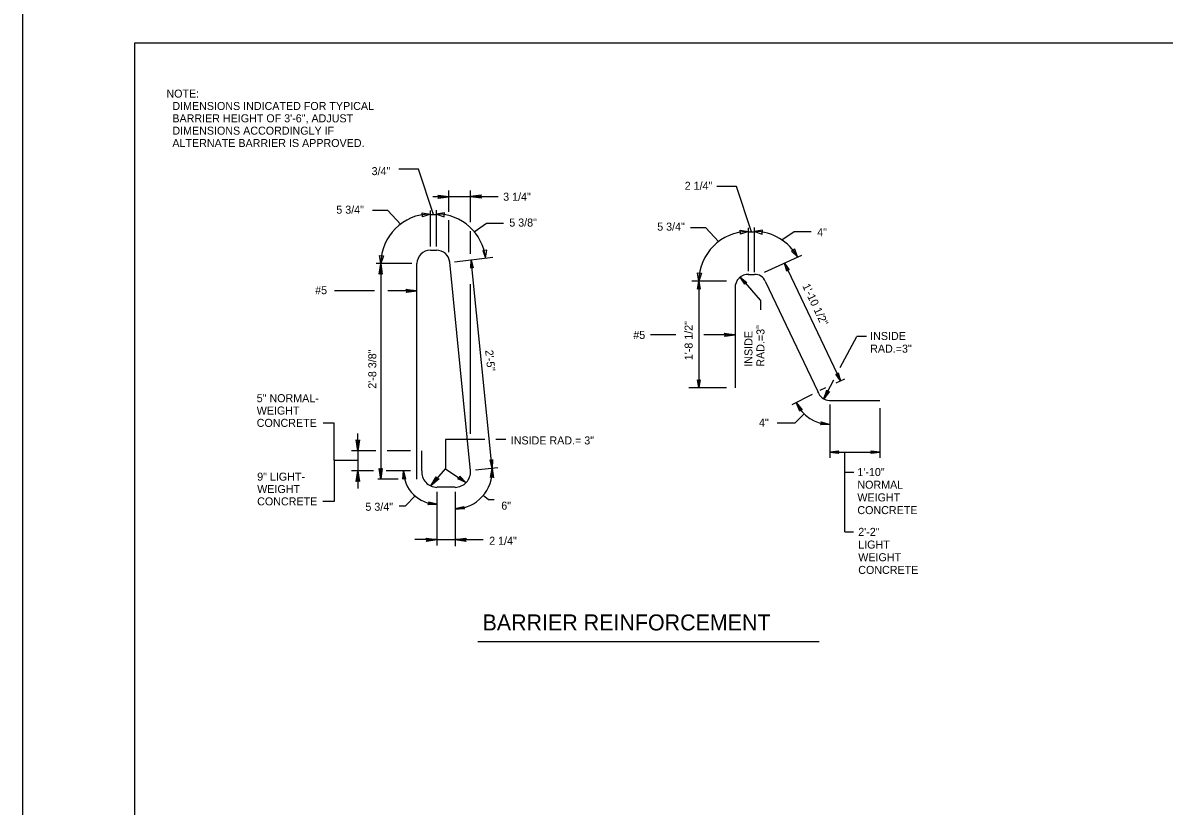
# Model space of a CAD drawing. Extents: x -24512 to -22484, y 4569 to 6351.
# Drawn here: x -24179.8 to -23752.2, y 4862.3 to 5155.5 of the extents above; entities that cross this region are included whole.
import ezdxf

# ---------------------------------------------------------------- set-up
doc = ezdxf.new("R2010")
doc.units = 0
for name, color, linetype in [('10', 7, 'Continuous'), ('11', 7, 'Continuous'), ('2', 7, 'Continuous'), ('PLT-BNDY', 7, 'Continuous')]:
    doc.layers.add(name, color=color, linetype=linetype)

msp = doc.modelspace()

# ---------------------------------------------------------------- linework, layer by layer
at = {"layer": '10'}
msp.add_arc((-24024.54, 4987.88), 12.58, 180.3102, 269.7376, dxfattribs=at)
at = {"layer": '11'}
msp.add_line((-24009.29, 4923.94), (-23881.36, 4923.94), dxfattribs=at)
at = {"layer": '2'}
for p, q in [((-24137.79, 5148.04), (-23353.75, 5148.04)), ((-24137.79, 4584.04), (-24137.79, 5148.04)), ((-24031.48, 5100.79), (-24038.95, 5100.79)), ((-24025.88, 5083.82), (-24031.48, 5100.79)), ((-24020.1, 5084.77), (-24020.1, 5092.81)), ((-24012.1, 5080.97), (-24012.1, 5092.81)), ((-23912.34, 5094.25), (-23919.81, 5094.25)), ((-23906.74, 5077.28), (-23912.34, 5094.25)), ((-24020.1, 5090.43), (-24026.19, 5090.43)), ((-24020.1, 5090.56), (-24020.1, 5090.56)), ((-24020.1, 5090.56), (-24012.1, 5090.56)), ((-24012.1, 5090.56), (-24012.1, 5090.56)), ((-24012.1, 5090.56), (-24001.73, 5090.56)), ((-24012.1, 5090.43), (-24012.1, 5090.43)), ((-24042.98, 5085.32), (-24048.81, 5085.32)), ((-24038.26, 5080.2), (-24042.98, 5085.32)), ((-24027.09, 5071.78), (-24027.09, 5085.33)), ((-24024.8, 5071.78), (-24024.8, 5085.42)), ((-24027.09, 5083.82), (-24024.8, 5083.82)), ((-24020.1, 5069.69), (-24020.1, 5081.65)), ((-24010.63, 5077.36), (-24006.04, 5080.56)), ((-24006.04, 5080.56), (-23999.66, 5080.56)), ((-24012.1, 5069.01), (-24012.1, 5077.57)), ((-23923.84, 5078.77), (-23929.68, 5078.77)), ((-23919.12, 5073.66), (-23923.84, 5078.77)), ((-23907.95, 5062.57), (-23907.95, 5078.78)), ((-23907.95, 5077.28), (-23905.66, 5077.28)), ((-23905.66, 5062.21), (-23905.66, 5078.88)), ((-23895.37, 5074.29), (-23890.78, 5077.49)), ((-23890.78, 5077.49), (-23884.4, 5077.49)), ((-24027.09, 5070.43), (-24024.8, 5070.43)), ((-24026.1, 5070.43), (-24026.1, 5070.43)), ((-24018.06, 5066.07), (-24003.67, 5067.79)), ((-23901.86, 5062.17), (-23887.96, 5068.61)), ((-24034, 5065.43), (-24047.39, 5065.43)), ((-24045.59, 5065.43), (-24045.59, 4984.68)), ((-24032.09, 4984.68), (-24032.09, 5065.43)), ((-24012.1, 4987.81), (-24019.82, 5065.92)), ((-24003.98, 4988.68), (-24011.78, 5066.82)), ((-23894.45, 5065.56), (-23873.45, 5021.56)), ((-23916.08, 5058.81), (-23929.14, 5058.81)), ((-23926.51, 5058.81), (-23926.51, 5018.93)), ((-23903.43, 5051.78), (-23910.68, 5060.03)), ((-23907.95, 5061.35), (-23905.66, 5061.35)), ((-23907.95, 5061.35), (-23905.66, 5061.35)), ((-23901.63, 5058.79), (-23881.95, 5017.56)), ((-24048.02, 5055.22), (-24063, 5055.22)), ((-24032.09, 5055.22), (-24042.98, 5055.22)), ((-24012.1, 5001.68), (-24012.1, 5057.65)), ((-23912.93, 5056.53), (-23912.95, 5018.93)), ((-23906.7, 5055.93), (-23906.7, 5055.93)), ((-23903.43, 5051.78), (-23903.43, 5048.05)), ((-23935.13, 5038.72), (-23944.61, 5038.72)), ((-23912.94, 5038.72), (-23924.6, 5038.72)), ((-23873.5, 5026.53), (-23867.32, 5038.18)), ((-23863.7, 5038.18), (-23867.32, 5038.18)), ((-23879.7, 5014.81), (-23875.92, 5021.92)), ((-23875.2, 5020.81), (-23875.2, 5020.81)), ((-23875.04, 5020.79), (-23871.82, 5022.31)), ((-23916.08, 5018.93), (-23930.29, 5018.93)), ((-23921.07, 5018.93), (-23921.07, 5018.93)), ((-23912.95, 5018.93), (-23912.95, 5018.93)), ((-23912.95, 5018.93), (-23912.95, 5018.93)), ((-23891.57, 5012.68), (-23883.86, 5016.54)), ((-23881, 5017.97), (-23878.94, 5019)), ((-23877.45, 5018.93), (-23877.45, 5018.93)), ((-23879.57, 5014.68), (-23879.57, 5014.68)), ((-23877.45, 5014.18), (-23858.7, 5014.18)), ((-23877.45, 5014.18), (-23877.45, 5014.18)), ((-23877.45, 5014.18), (-23877.45, 5014.18)), ((-23877.45, 5012.68), (-23877.45, 4992.94)), ((-23877.45, 5011.33), (-23877.45, 4992.73)), ((-23858.7, 5014.18), (-23858.7, 5014.18)), ((-23858.7, 5011.33), (-23858.7, 4992.73)), ((-23887.19, 5009.06), (-23890.42, 5005.79)), ((-24063.08, 5005.68), (-24067.21, 5005.68)), ((-24063.08, 4991.68), (-24063.08, 5005.68)), ((-23897.16, 5005.79), (-23890.42, 5005.79)), ((-24054.21, 4995.31), (-24054.21, 5001.79)), ((-24021.35, 4999.56), (-24021.35, 4988.56)), ((-24006.73, 4999.56), (-24021.35, 4999.56)), ((-23998.85, 4999.56), (-24002.6, 4999.56)), ((-24047.56, 4995.31), (-24056.59, 4995.31)), ((-24054.21, 4995.31), (-24054.21, 4981.24)), ((-24034.57, 4995.31), (-24043.21, 4995.31)), ((-24037.34, 4995.31), (-24037.34, 4995.31)), ((-24030.32, 4987.89), (-24030.32, 4995.31)), ((-23877.45, 4994.85), (-23858.7, 4994.85)), ((-23877.45, 4994.85), (-23877.45, 4994.85)), ((-23871.82, 4964.99), (-23871.82, 4994.73)), ((-23858.7, 4994.85), (-23858.7, 4994.85)), ((-24054.21, 4991.68), (-24063.08, 4991.68)), ((-24063.08, 4991.68), (-24063.08, 4976.31)), ((-24048.34, 4987.81), (-24056.59, 4987.81)), ((-24034.57, 4987.81), (-24043.59, 4987.81)), ((-24026.88, 4982.16), (-24021.35, 4988.56)), ((-24021.35, 4988.56), (-24013.73, 4983.43)), ((-24012.1, 4987.81), (-24012.1, 4987.81)), ((-24010.23, 4988.18), (-24001.85, 4989.06)), ((-24003.98, 4988.93), (-24003.98, 4988.93)), ((-23871.82, 4987.35), (-23868.45, 4987.35)), ((-24039.1, 4984.68), (-24046.7, 4984.68)), ((-24032.09, 4984.68), (-24032.09, 4984.68)), ((-24026.1, 4983.06), (-24026.1, 4983.06)), ((-24017.73, 4981.68), (-24024.6, 4981.68)), ((-24022.6, 4981.68), (-24022.6, 4981.68)), ((-24018.85, 4981.68), (-24018.85, 4981.68)), ((-24017.73, 4981.68), (-24017.73, 4981.68)), ((-24013.73, 4983.43), (-24013.73, 4983.43)), ((-24036.34, 4974.68), (-24032.79, 4978.49)), ((-24024.6, 4979.93), (-24024.6, 4959.93)), ((-24017.73, 4979.93), (-24017.73, 4959.68)), ((-24005.35, 4976.93), (-24007.27, 4978.6)), ((-24063.08, 4976.31), (-24067.33, 4976.31)), ((-24038.77, 4974.68), (-24036.34, 4974.68)), ((-24003.23, 4976.93), (-24005.35, 4976.93)), ((-23871.82, 4964.99), (-23868.57, 4964.99)), ((-24024.6, 4962.06), (-24032.85, 4962.06)), ((-24024.6, 4962.06), (-24007.35, 4962.06)), ((-24017.73, 4962.06), (-24017.73, 4962.06))]:
    msp.add_line(p, q, dxfattribs=at)
for points in [[(-24024.1, 5090.93), (-24023.85, 5090.56), (-24020.1, 5090.43), (-24024.1, 5090.93), (-24024.23, 5091.06), (-24020.1, 5090.43), (-24023.85, 5090.31), (-24024.1, 5089.93), (-24020.1, 5090.43), (-24024.23, 5089.81), (-24024.1, 5089.93)], [(-24024.1, 5090.93), (-24023.85, 5090.56), (-24020.1, 5090.43), (-24024.1, 5090.93), (-24024.23, 5091.06), (-24020.1, 5090.43), (-24023.85, 5090.31), (-24024.1, 5089.93), (-24020.1, 5090.43), (-24024.23, 5089.81), (-24024.1, 5089.93)], [(-24008.1, 5090.06), (-24008.35, 5090.43), (-24012.1, 5090.56), (-24008.1, 5090.06), (-24007.98, 5089.93), (-24012.1, 5090.56), (-24008.35, 5090.68), (-24008.1, 5091.06), (-24012.1, 5090.56), (-24007.98, 5091.18), (-24008.1, 5091.06)], [(-24046.09, 5061.56), (-24045.84, 5061.68), (-24045.59, 5065.43), (-24046.09, 5061.56), (-24046.21, 5061.43), (-24045.59, 5065.43), (-24045.46, 5061.68), (-24045.21, 5061.56), (-24045.59, 5065.43), (-24045.09, 5061.43), (-24045.21, 5061.56)], [(-24011.91, 5063.94), (-24011.66, 5064.07), (-24011.78, 5066.82), (-24011.91, 5063.94), (-24011.91, 5063.69), (-24011.78, 5066.82), (-24011.41, 5064.07), (-24011.16, 5063.94), (-24011.78, 5066.82), (-24011.03, 5063.82), (-24011.16, 5063.94)], [(-23893.57, 5062.81), (-23893.32, 5062.93), (-23894.45, 5065.56), (-23893.57, 5062.81), (-23893.57, 5062.56), (-23894.45, 5065.56), (-23893.07, 5063.06), (-23892.95, 5063.06), (-23894.45, 5065.56), (-23892.7, 5063.06), (-23892.95, 5063.06)], [(-23926.89, 5055.93), (-23926.64, 5056.06), (-23926.51, 5058.81), (-23926.89, 5055.93), (-23927.01, 5055.81), (-23926.51, 5058.81), (-23926.39, 5056.06), (-23926.14, 5055.93), (-23926.51, 5058.81), (-23926.01, 5055.81), (-23926.14, 5055.93)], [(-23909.33, 5057.99), (-23909.21, 5058.11), (-23910.96, 5060.36), (-23909.33, 5057.99), (-23909.33, 5057.74), (-23910.96, 5060.36), (-23908.96, 5058.36), (-23908.83, 5058.36), (-23910.96, 5060.36), (-23908.58, 5058.36), (-23908.83, 5058.36)], [(-24035.96, 5055.6), (-24035.84, 5055.35), (-24032.09, 5055.22), (-24035.96, 5055.6), (-24036.09, 5055.85), (-24032.09, 5055.22), (-24035.84, 5055.1), (-24035.96, 5054.72), (-24032.09, 5055.22), (-24036.09, 5054.6), (-24035.96, 5054.72)], [(-23916.82, 5039.1), (-23916.69, 5038.85), (-23912.94, 5038.72), (-23916.82, 5039.1), (-23916.94, 5039.35), (-23912.94, 5038.72), (-23916.69, 5038.6), (-23916.82, 5038.22), (-23912.94, 5038.72), (-23916.94, 5038.1), (-23916.82, 5038.22)], [(-23874.32, 5024.31), (-23874.57, 5024.18), (-23873.45, 5021.56), (-23874.32, 5024.31), (-23874.32, 5024.56), (-23873.45, 5021.56), (-23874.82, 5024.06), (-23874.95, 5024.06), (-23873.45, 5021.56), (-23875.2, 5024.06), (-23874.95, 5024.06)], [(-23926.14, 5021.81), (-23926.39, 5021.68), (-23926.51, 5018.93), (-23926.14, 5021.81), (-23926.01, 5021.93), (-23926.51, 5018.93), (-23926.64, 5021.68), (-23926.89, 5021.81), (-23926.51, 5018.93), (-23927.01, 5021.93), (-23926.89, 5021.81)], [(-23877.82, 5017.43), (-23878.07, 5017.43), (-23879.7, 5014.81), (-23877.82, 5017.43), (-23877.57, 5017.56), (-23879.7, 5014.81), (-23878.32, 5017.56), (-23878.57, 5017.81), (-23879.7, 5014.81), (-23878.57, 5018.06), (-23878.57, 5017.81)], [(-23888.65, 5010.38), (-23888.5, 5010.61), (-23890, 5013.35), (-23888.65, 5010.38), (-23888.7, 5010.2), (-23890, 5013.35), (-23888.29, 5010.74), (-23888.01, 5010.76), (-23890, 5013.35), (-23887.84, 5010.72), (-23888.01, 5010.76)], [(-23880.7, 5006), (-23880.53, 5005.78), (-23877.49, 5005.22), (-23880.7, 5006), (-23880.73, 5006.12), (-23877.49, 5005.22), (-23880.58, 5005.39), (-23880.68, 5005.24), (-23877.49, 5005.22), (-23880.9, 5005.07), (-23880.68, 5005.24)], [(-24053.71, 4999.18), (-24054.09, 4999.06), (-24054.21, 4995.31), (-24053.71, 4999.18), (-24053.59, 4999.43), (-24054.21, 4995.31), (-24054.34, 4999.06), (-24054.59, 4999.18), (-24054.21, 4995.31), (-24054.84, 4999.43), (-24054.59, 4999.18)], [(-23874.2, 4994.48), (-23874.32, 4994.73), (-23877.45, 4994.85), (-23874.2, 4994.48), (-23874.07, 4994.35), (-23877.45, 4994.85), (-23874.32, 4994.98), (-23874.2, 4995.23), (-23877.45, 4994.85), (-23874.07, 4995.35), (-23874.2, 4995.23)], [(-23874.2, 4994.48), (-23874.32, 4994.73), (-23877.45, 4994.85), (-23874.2, 4994.48), (-23874.07, 4994.35), (-23877.45, 4994.85), (-23874.32, 4994.98), (-23874.2, 4995.23), (-23877.45, 4994.85), (-23874.07, 4995.35), (-23874.2, 4995.23)], [(-23861.95, 4995.23), (-23861.82, 4994.98), (-23858.7, 4994.85), (-23861.95, 4995.23), (-23862.07, 4995.35), (-23858.7, 4994.85), (-23861.82, 4994.73), (-23861.95, 4994.48), (-23858.7, 4994.85), (-23862.07, 4994.35), (-23861.95, 4994.48)], [(-24003.85, 4991.81), (-24004.1, 4991.68), (-24003.98, 4988.68), (-24003.85, 4991.81), (-24003.85, 4992.06), (-24003.98, 4988.68), (-24004.35, 4991.68), (-24004.6, 4991.81), (-24003.98, 4988.68), (-24004.73, 4991.93), (-24004.6, 4991.81)], [(-24054.59, 4983.93), (-24054.34, 4984.06), (-24054.21, 4987.81), (-24054.59, 4983.93), (-24054.84, 4983.81), (-24054.21, 4987.81), (-24054.09, 4984.06), (-24053.71, 4983.93), (-24054.21, 4987.81), (-24053.59, 4983.81), (-24053.71, 4983.93)], [(-24045.21, 4988.56), (-24045.46, 4988.43), (-24045.59, 4984.68), (-24045.21, 4988.56), (-24045.09, 4988.68), (-24045.59, 4984.68), (-24045.84, 4988.43), (-24046.09, 4988.56), (-24045.59, 4984.68), (-24046.21, 4988.68), (-24046.09, 4988.56)], [(-24037.24, 4984.79), (-24037, 4984.93), (-24037.12, 4987.81), (-24037.24, 4984.79), (-24037.36, 4984.65), (-24037.12, 4987.81), (-24036.75, 4984.95), (-24036.49, 4984.85), (-24037.12, 4987.81), (-24036.36, 4984.74), (-24036.49, 4984.85)], [(-24016.1, 4985.56), (-24016.1, 4985.43), (-24013.73, 4983.43), (-24016.1, 4985.56), (-24016.1, 4985.81), (-24013.73, 4983.43), (-24016.23, 4985.06), (-24016.6, 4984.93), (-24013.73, 4983.43), (-24016.73, 4984.81), (-24016.6, 4984.93)], [(-24004.41, 4985.47), (-24004.27, 4985.58), (-24003.92, 4988.69), (-24004.41, 4985.47), (-24004.55, 4985.36), (-24003.92, 4988.69), (-24003.9, 4985.54), (-24003.52, 4985.5), (-24003.92, 4988.69), (-24003.43, 4985.23), (-24003.52, 4985.5)], [(-24024.13, 4984.79), (-24024.38, 4984.79), (-24026.88, 4982.16), (-24024.13, 4984.79), (-24023.75, 4984.79), (-24026.88, 4982.16), (-24024.63, 4985.16), (-24024.88, 4985.41), (-24026.88, 4982.16), (-24024.88, 4985.54), (-24024.88, 4985.41)], [(-24027.65, 4976.11), (-24027.55, 4975.85), (-24024.6, 4975.29), (-24027.65, 4976.11), (-24027.77, 4976.25), (-24024.6, 4975.29), (-24027.58, 4975.6), (-24027.73, 4975.36), (-24024.6, 4975.29), (-24028, 4975.14), (-24027.73, 4975.36)], [(-24014.48, 4973.77), (-24014.74, 4973.86), (-24017.73, 4973.57), (-24014.48, 4973.77), (-24014.34, 4973.66), (-24017.73, 4973.57), (-24014.8, 4974.23), (-24014.57, 4974.39), (-24017.73, 4973.57), (-24014.46, 4974.53), (-24014.57, 4974.39)], [(-24028.47, 4962.43), (-24028.35, 4962.18), (-24024.6, 4962.06), (-24028.47, 4962.43), (-24028.6, 4962.68), (-24024.6, 4962.06), (-24028.35, 4961.93), (-24028.47, 4961.56), (-24024.6, 4962.06), (-24028.6, 4961.43), (-24028.47, 4961.56)], [(-24013.85, 4961.56), (-24013.98, 4961.93), (-24017.73, 4962.06), (-24013.85, 4961.56), (-24013.73, 4961.43), (-24017.73, 4962.06), (-24013.98, 4962.18), (-24013.85, 4962.43), (-24017.73, 4962.06), (-24013.73, 4962.68), (-24013.85, 4962.43)]]:
    msp.add_lwpolyline(points, dxfattribs=at)
for points in [[(-24030.14, 5084.46), (-24027.09, 5083.95), (-24030.02, 5082.96)], [(-24021.74, 5084.46), (-24024.8, 5083.95), (-24021.87, 5082.96)], [(-23911, 5077.91), (-23907.95, 5077.41), (-23910.88, 5076.42)], [(-23902.61, 5077.91), (-23905.66, 5077.41), (-23902.73, 5076.42)], [(-24044.62, 5068.36), (-24045.61, 5065.43), (-24046.11, 5068.48)], [(-24007.41, 5070.36), (-24006.42, 5067.43), (-24005.91, 5070.48)], [(-23891.76, 5070.02), (-23889.49, 5067.92), (-23890.51, 5070.84)], [(-23925.48, 5061.82), (-23926.47, 5058.89), (-23926.97, 5061.94)]]:
    msp.add_lwpolyline(points, close=True, dxfattribs=at)
for centre, radius, start, end in [((-24027.09, 5065.43), 18.52, 90, 180), ((-24024.8, 5065.43), 18.52, 6.2905, 90), ((-23907.95, 5058.89), 18.52, 90, 180), ((-23905.66, 5058.89), 18.52, 29.1286, 90), ((-24027.09, 5065.43), 5, 90, 180), ((-24024.8, 5065.43), 5, 5.6406, 90), ((-23907.98, 5056.4), 4.95, 87.3887, 181.3954), ((-23905.33, 5057.42), 3.95, 20.4906, 94.8279), ((-23877.49, 5018.9), 4.69, 196.5463, 270), ((-23877.49, 5018.9), 13.69, 203.7774, 270), ((-24024.5, 4987.49), 5.84, 176.0632, 269.0423), ((-24018.16, 4987.77), 14.24, 271.5074, 3.9368), ((-24017.88, 4987.49), 5.84, 270.9577, 3.9368)]:
    msp.add_arc(centre, radius, start, end, dxfattribs=at)
at = {"layer": 'PLT-BNDY'}
msp.add_lwpolyline([(-24179.75, 5163.04), (-23338.75, 5163.04), (-23338.75, 4569.04), (-24179.75, 4569.04)], close=True, dxfattribs=at)

# ---------------------------------------------------------------- texts
at = {"layer": '10'}
for p in [(-24070.24, 5053.96), (-23951.05, 5037.21)]:
    msp.add_text('#5', height=3, dxfattribs=at).set_placement(p)
at = {"layer": '11'}
msp.add_text('BARRIER REINFORCEMENT', height=6.0008, dxfattribs=at).set_placement((-24007.53, 4928.07))
at = {"layer": '2'}
for s, height, p in [('NOTE:', 2.999, (-24125.96, 5127.55)), ('  DIMENSIONS INDICATED FOR TYPICAL', 2.9992, (-24125.96, 5122.92)), ('  BARRIER HEIGHT OF 3\'-6", ADJUST', 2.9992, (-24125.96, 5118.3)), ('  DIMENSIONS ACCORDINGLY IF', 2.9992, (-24125.96, 5113.68)), ('  ALTERNATE BARRIER IS APPROVED.', 2.9992, (-24125.96, 5109.05)), ('3/4"', 2.999, (-24049.09, 5098.53)), ('2 1/4"', 2.999, (-23931.8, 5093.04)), ('3 1/4"', 2.999, (-23999.79, 5088.95)), ('5 3/4"', 2.999, (-24062.31, 5084.1)), ('5 3/8"', 2.999, (-23997.51, 5079.27)), ('5 3/4"', 2.999, (-23942.1, 5077.75)), ('4"', 2.999, (-23882.17, 5075.63)), ('INSIDE', 3, (-23862.32, 5036.82)), ('RAD.=3"', 3, (-23862.32, 5032.07)), ('5" NORMAL- ', 2.9992, (-24092.13, 5013.53)), ('WEIGHT', 2.999, (-24092.13, 5008.9)), ('CONCRETE', 2.999, (-24092.13, 5004.28)), ('4"', 2.999, (-23903.97, 5004.4)), ('9" LIGHT- ', 2.999, (-24091.96, 4984.15)), ('1\'-10" ', 3, (-23867.11, 4985.88)), ('WEIGHT', 2.999, (-24091.96, 4979.52)), ('NORMAL', 3, (-23867.11, 4981.13)), ('CONCRETE', 2.999, (-24091.96, 4974.9)), ('WEIGHT', 3, (-23867.11, 4976.38)), ('5 3/4"', 2.999, (-24051.41, 4972.88)), ('6"', 2.999, (-24000.51, 4973.29)), ('CONCRETE', 3, (-23867.11, 4971.63)), ('2\'-2"', 3, (-23866.78, 4963.48)), ('2 1/4"', 2.999, (-24005.04, 4960.16)), ('LIGHT', 3, (-23866.78, 4958.73)), ('WEIGHT', 3, (-23866.78, 4953.98)), ('CONCRETE', 3, (-23866.78, 4949.23))]:
    msp.add_text(s, height=height, dxfattribs=at).set_placement(p)
for s, height, rotation, p in [('1\'-10 1/2"', 3, 295.3984, (-23887.83, 5057.09)), ('1\'-8 1/2"', 3, 90, (-23928.84, 5029.23)), ('RAD.=3"', 3, 90, (-23901.91, 5026.81)), ('INSIDE', 3, 90, (-23906.41, 5026.81)), ('2\'-8 3/8"', 2.999, 90, (-24047.34, 5018.57)), ('2\'-5"', 2.999, 275.8377, (-24006.55, 5032.95)), ('INSIDE RAD.= 3"', 2.9992, 360, (-23996.95, 4997.71))]:
    msp.add_text(s, height=height, rotation=rotation, dxfattribs=at).set_placement(p)

doc.saveas('drawing.dxf')
